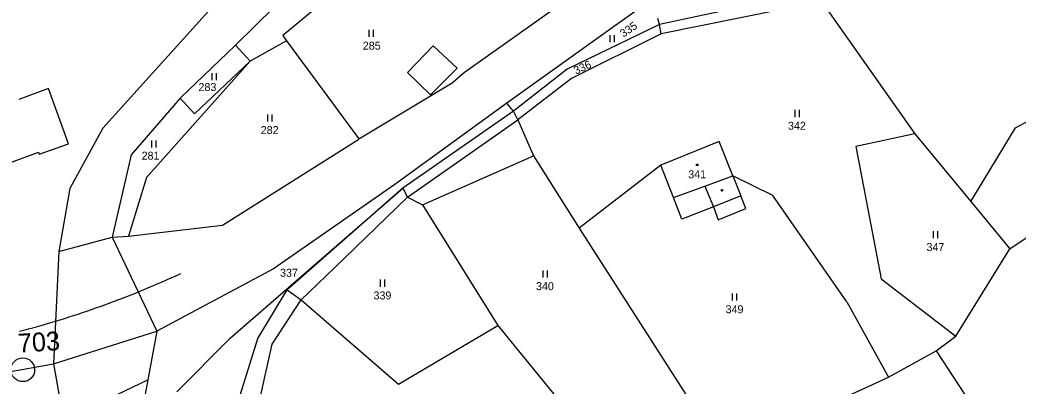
# Model space of a CAD drawing. Extents: x -670359 to -668019, y -978807 to -976674.
# Drawn here: x -669241.5 to -669029.4, y -977159.1 to -977081.3 of the extents above; entities that cross this region are included whole.
import ezdxf

# ---------------------------------------------------------------- set-up
doc = ezdxf.new("R2010")
doc.units = 0
for name, color, linetype in [('Hranice parcel', 7, 'Continuous'), ('Navazující stavba', 7, 'Continuous'), ('Parcelní čísla', 7, 'Continuous'), ('Související stavba', 7, 'Continuous'), ('Vnitřní kresba', 7, 'Continuous'), ('Značky budov', 7, 'Continuous'), ('Značky kultur', 7, 'Continuous'), ('ŽBP', 7, 'Continuous')]:
    doc.layers.add(name, color=color, linetype=linetype)

msp = doc.modelspace()

# ---------------------------------------------------------------- linework, layer by layer
at = {"layer": 'Hranice parcel'}
for points in [[(-669175.21, -977066.43), (-669195.69, -977086.62)], [(-669170.18, -977071.73), (-669185.64, -977084.61)], [(-669070.99, -977074.8), (-669105.55, -977082.22)], [(-669147.03, -977092.35), (-669124.88, -977076.65)], [(-669200.15, -977077.96), (-669223.85, -977104.3)], [(-669108.55, -977077.9), (-669116.1, -977083.32)], [(-669071.17, -977077.39), (-669105.25, -977084.23)], [(-669071.17, -977077.39), (-669051.32, -977105.5)], [(-669105.55, -977082.22), (-669105.92, -977080.95)], [(-669116.1, -977083.32), (-669138.01, -977098.94)], [(-669105.55, -977082.22), (-669125.16, -977091.74)], [(-669105.25, -977084.23), (-669105.55, -977082.22)], [(-669185.64, -977084.61), (-669184.8, -977085.69)], [(-669105.25, -977084.23), (-669124.27, -977093.72)], [(-669029.93, -977104.2), (-668995.44, -977085.57)], [(-669195.69, -977086.62), (-669207.42, -977097.87)], [(-669192.58, -977090.07), (-669195.69, -977086.62)], [(-669184.8, -977085.69), (-669192.58, -977090.07)], [(-669184.8, -977085.69), (-669169.48, -977106.54)], [(-669192.58, -977090.07), (-669214.6, -977114.73)], [(-669192.58, -977090.07), (-669204.39, -977101.23)], [(-669125.16, -977091.74), (-669136.58, -977100.7)], [(-669149.6, -977094.67), (-669147.03, -977092.35)], [(-669124.27, -977093.72), (-669135.69, -977102.51)], [(-669235.38, -977095.86), (-669241.7, -977098.19)], [(-669231.13, -977107.63), (-669235.38, -977095.86)], [(-669169.48, -977106.54), (-669149.6, -977094.67)], [(-669207.42, -977097.87), (-669217.87, -977109.92)], [(-669204.39, -977101.23), (-669207.42, -977097.87)], [(-669138.01, -977098.94), (-669161.84, -977116.23)], [(-669136.58, -977100.7), (-669138.01, -977098.94)], [(-669136.58, -977100.7), (-669160.1, -977117)], [(-669135.69, -977102.51), (-669136.58, -977100.7)], [(-669135.69, -977102.51), (-669132.36, -977110.16)], [(-669223.85, -977104.3), (-669230.86, -977117.08)], [(-669039.43, -977119.85), (-669029.93, -977104.2)], [(-669198.42, -977124.93), (-669169.67, -977106.76)], [(-669169.67, -977106.76), (-669169.48, -977106.54)], [(-669051.32, -977105.5), (-669063.82, -977108.18)], [(-669051.32, -977105.5), (-669039.43, -977119.85)], [(-669237.37, -977109.84), (-669231.13, -977107.63)], [(-669092.88, -977107.14), (-669105.3, -977112.15)], [(-669090, -977114.38), (-669092.88, -977107.14)], [(-669063.82, -977108.18), (-669058.46, -977136.28)], [(-669276.7, -977123.85), (-669237.53, -977109.41)], [(-669237.53, -977109.41), (-669237.37, -977109.84)], [(-669217.87, -977109.92), (-669221.85, -977127.43)], [(-669132.36, -977110.16), (-669122.64, -977125.54)], [(-669105.3, -977112.15), (-669122.64, -977125.54)], [(-669102.6, -977119.04), (-669105.3, -977112.15)], [(-669214.6, -977114.73), (-669218.41, -977127.2)], [(-669081.46, -977118.62), (-669090, -977114.38)], [(-669090, -977114.38), (-669088.28, -977118.68)], [(-669230.86, -977117.08), (-669233.23, -977130.52)], [(-669196.78, -977148.94), (-669160.1, -977117)], [(-669161.84, -977116.23), (-669187.58, -977134.18)], [(-669160.1, -977117), (-669184.66, -977138.65)], [(-669160.1, -977117), (-669159.13, -977118.96)], [(-669159.13, -977118.96), (-669155.93, -977120.57)], [(-669100.81, -977123.61), (-669102.6, -977119.04)], [(-669088.28, -977118.68), (-669094.12, -977120.98)], [(-669065.77, -977141.22), (-669081.46, -977118.62)], [(-669155.93, -977120.57), (-669139.93, -977146.22)], [(-669094.12, -977120.98), (-669100.81, -977123.61)], [(-669039.43, -977119.85), (-669031.15, -977129.95)], [(-669218.41, -977127.2), (-669198.42, -977124.93)], [(-669122.64, -977125.54), (-669092.76, -977172.16)], [(-669233.23, -977130.52), (-669221.85, -977127.43)], [(-669221.85, -977127.43), (-669218.41, -977127.2)], [(-669031.15, -977129.95), (-669025.76, -977126.29)], [(-669042.57, -977148.49), (-669031.15, -977129.95)], [(-669187.58, -977134.18), (-669212.37, -977147.43)], [(-669058.46, -977136.28), (-669042.57, -977148.49)], [(-669190.94, -977148.96), (-669184.66, -977138.65)], [(-669184.66, -977138.65), (-669181.7, -977140.74)], [(-669181.7, -977140.74), (-669161.03, -977158.72)], [(-669065.77, -977141.22), (-669056.93, -977157.17)], [(-669161.03, -977158.72), (-669139.93, -977146.22)], [(-669139.93, -977146.22), (-669116.72, -977174.68)], [(-669234.31, -977154.34), (-669212.37, -977147.43)], [(-669212.37, -977147.43), (-669214.32, -977157.79)], [(-669208.11, -977160.35), (-669196.78, -977148.94)], [(-669194.66, -977161.03), (-669190.94, -977148.96)], [(-669046.76, -977151.63), (-669042.57, -977148.49)], [(-669056.93, -977157.17), (-669046.76, -977151.63)], [(-669046.76, -977151.63), (-669025.88, -977183.58)], [(-669244.61, -977156.24), (-669234.31, -977154.34)], [(-669082.92, -977169.18), (-669056.93, -977157.17)], [(-669214.32, -977157.79), (-669215.81, -977165.77)]]:
    msp.add_lwpolyline(points, dxfattribs=at)
at = {"layer": 'Navazující stavba'}
msp.add_lwpolyline([(-669241.59, -977147.46), (-669240.63, -977147.21), (-669239.66, -977146.95), (-669238.7, -977146.69), (-669237.73, -977146.42), (-669236.77, -977146.15), (-669235.81, -977145.87), (-669234.85, -977145.59), (-669233.89, -977145.3), (-669232.93, -977145.01), (-669231.98, -977144.71), (-669231.03, -977144.41), (-669230.07, -977144.1), (-669229.12, -977143.79), (-669228.17, -977143.48), (-669227.23, -977143.16), (-669226.28, -977142.83), (-669225.34, -977142.5), (-669224.39, -977142.17), (-669223.45, -977141.83), (-669222.51, -977141.49), (-669221.58, -977141.14), (-669220.64, -977140.79), (-669219.71, -977140.43), (-669218.78, -977140.07), (-669217.85, -977139.7), (-669216.92, -977139.33), (-669215.99, -977138.95), (-669215.07, -977138.57), (-669214.14, -977138.18), (-669213.22, -977137.79), (-669212.3, -977137.4), (-669211.39, -977137), (-669210.47, -977136.6), (-669209.56, -977136.19), (-669208.65, -977135.78), (-669207.28, -977135.15)], dxfattribs=at)
at = {"layer": 'Související stavba'}
msp.add_lwpolyline([(-669241.59, -977147.46), (-669240.63, -977147.21), (-669239.66, -977146.95), (-669238.7, -977146.69), (-669237.73, -977146.42), (-669236.77, -977146.15), (-669235.81, -977145.87), (-669234.85, -977145.59), (-669233.89, -977145.3), (-669232.93, -977145.01), (-669231.98, -977144.71), (-669231.03, -977144.41), (-669230.07, -977144.1), (-669229.12, -977143.79), (-669228.17, -977143.48), (-669227.23, -977143.16), (-669226.28, -977142.83), (-669225.34, -977142.5), (-669224.39, -977142.17), (-669223.45, -977141.83), (-669222.51, -977141.49), (-669221.58, -977141.14), (-669220.64, -977140.79), (-669219.71, -977140.43), (-669218.78, -977140.07), (-669217.85, -977139.7), (-669216.92, -977139.33), (-669215.99, -977138.95), (-669215.07, -977138.57), (-669214.14, -977138.18), (-669213.22, -977137.79), (-669212.3, -977137.4), (-669211.39, -977137), (-669210.47, -977136.6), (-669209.56, -977136.19), (-669208.65, -977135.78), (-669207.28, -977135.15)], dxfattribs=at)
at = {"layer": 'Vnitřní kresba'}
for points in [[(-669159.12, -977092.48), (-669153.66, -977086.81)], [(-669153.66, -977086.81), (-669148.55, -977091.55)], [(-669149.03, -977092.03), (-669154.25, -977097.21)], [(-669148.55, -977091.55), (-669149.03, -977092.03)], [(-669154.25, -977097.21), (-669159.12, -977092.48)], [(-669159.13, -977118.96), (-669135.69, -977102.51)], [(-669155.93, -977120.57), (-669132.36, -977110.16)], [(-669095.95, -977116.58), (-669090, -977114.38)], [(-669102.6, -977119.04), (-669095.95, -977116.58)], [(-669095.95, -977116.58), (-669094.12, -977120.98)], [(-669159.13, -977118.96), (-669174.63, -977133.96)], [(-669087.24, -977121.32), (-669088.28, -977118.68)], [(-669094.12, -977120.98), (-669093.09, -977123.79)], [(-669093.09, -977123.79), (-669087.24, -977121.32)], [(-669221.85, -977127.43), (-669212.37, -977147.43)], [(-669233.23, -977130.52), (-669234.31, -977154.34)], [(-669174.63, -977133.96), (-669181.7, -977140.74)], [(-669187.9, -977150.17), (-669181.7, -977140.74)], [(-669190.5, -977161.92), (-669187.9, -977150.17)], [(-669234.31, -977154.34), (-669232.23, -977166.36)], [(-669232.23, -977166.36), (-669214.32, -977157.79)]]:
    msp.add_lwpolyline(points, dxfattribs=at)
at = {"layer": 'Značky budov'}
msp.add_circle((-669097.55, -977112.09), 0.175, dxfattribs=at)
at = {"layer": 'Značky kultur'}
for p, q in [((-669167.33, -977083.35), (-669167.33, -977084.85)), ((-669166.33, -977084.85), (-669166.33, -977083.35)), ((-669116.1, -977084.52), (-669116.1, -977086.02)), ((-669115.1, -977086.02), (-669115.1, -977084.52)), ((-669200.67, -977092.57), (-669200.67, -977094.07)), ((-669199.67, -977094.07), (-669199.67, -977092.57)), ((-669076.83, -977100.41), (-669076.83, -977101.91)), ((-669075.83, -977101.91), (-669075.83, -977100.41)), ((-669188.87, -977101.34), (-669188.87, -977102.84)), ((-669187.87, -977102.84), (-669187.87, -977101.34)), ((-669213.55, -977106.88), (-669213.55, -977108.38)), ((-669212.55, -977108.38), (-669212.55, -977106.88)), ((-669047.4, -977126.19), (-669047.4, -977127.69)), ((-669046.4, -977127.69), (-669046.4, -977126.19)), ((-669164.95, -977136.48), (-669164.95, -977137.98)), ((-669163.95, -977137.98), (-669163.95, -977136.48)), ((-669130.38, -977134.51), (-669130.38, -977136.01)), ((-669129.38, -977136.01), (-669129.38, -977134.51)), ((-669090.13, -977139.42), (-669090.13, -977140.92)), ((-669089.13, -977140.92), (-669089.13, -977139.42))]:
    msp.add_line(p, q, dxfattribs=at)
for centre in [(-669097.55, -977112.09), (-669092.27, -977117.47)]:
    msp.add_circle(centre, 0.175, dxfattribs=at)
at = {"layer": 'ŽBP'}
msp.add_circle((-669240.87, -977155.63), 2.52, dxfattribs=at)

# ---------------------------------------------------------------- texts
at = {"layer": 'Parcelní čísla'}
for s, rotation, p in [('335', 34.2869, (-669113.24, -977085.05)), ('336', 24.8314, (-669123.32, -977092.92))]:
    msp.add_text(s, height=1.7, rotation=rotation, dxfattribs=at).set_placement(p)
for s, p in [('285', (-669168.61, -977087.59)), ('283', (-669203.53, -977096.39)), ('282', (-669190.3, -977105.54)), ('342', (-669078.26, -977104.61)), ('281', (-669215.62, -977110.98)), ('341', (-669099.46, -977114.93)), ('347', (-669048.83, -977130.39)), ('337', (-669186.2, -977135.86)), ('340', (-669131.81, -977138.71)), ('339', (-669166.34, -977140.68)), ('349', (-669091.52, -977143.62))]:
    msp.add_text(s, height=1.7, dxfattribs=at).set_placement(p)
at = {"layer": 'ŽBP'}
msp.add_text('GB 703', height=4, rotation=3.5184, dxfattribs=at).set_placement((-669250.97, -977152.56))

doc.saveas('drawing.dxf')
